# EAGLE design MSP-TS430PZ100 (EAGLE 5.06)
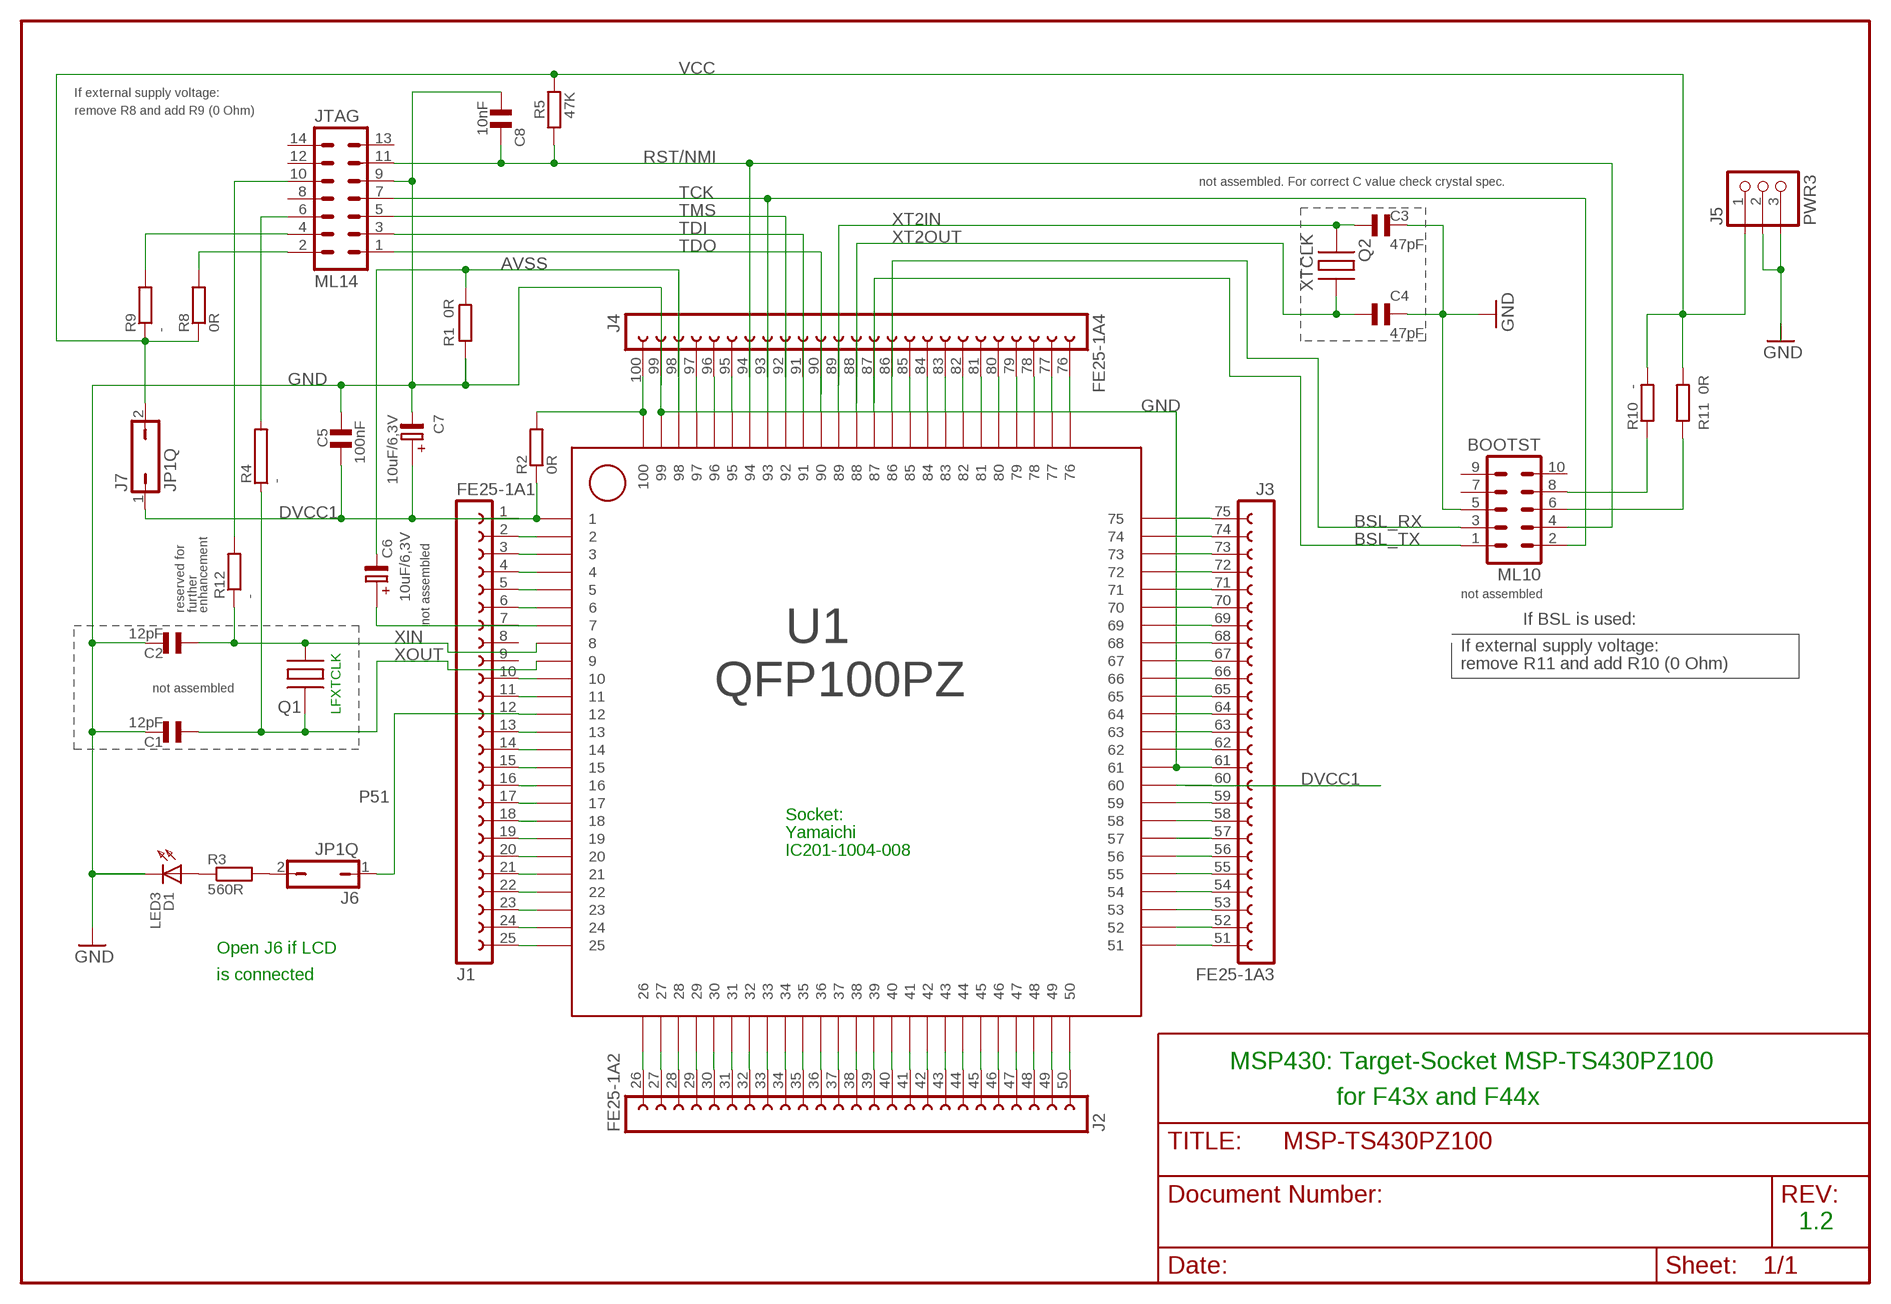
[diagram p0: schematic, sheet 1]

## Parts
BOOTST  ML10  [ML10]
C1  12pF  CSMD0805  [CSMD0805]
C2  12pF  CSMD0805  [CSMD0805]
C3  47pF  CSMD0805  [CSMD0805]
C4  47pF  CSMD0805  [CSMD0805]
C5  100nF  CSMD0805  [CSMD0805]
C6  10uF/6,3V  ELKO_1210  [1210ELKO]
C7  10uF/6,3V  ELKO_1210  [1210ELKO]
C8  10nF  CSMD0805  [CSMD0805]
D1  LED3  [LED3]
J1  FE25-1A1  [FE25-1A1]
J2  FE25-1A2  [FE25-1A2]
J3  FE25-1A3  [FE25-1A3]
J4  FE25-1A4  [FE25-1A4]
J5  PWR3  [PWR3]
J6  JP1Q  [JP1]
J7  JP1Q  [JP1]
JTAG  ML14  [ML14]
Q1  QUARZ3  [QUARZ3]
Q2  XTCLK  QUARZ2  [QUARZ2]
R1  0R  R_0805  [0805]
R2  0R  R_0805  [0805]
R3  560R  R_0805  [0805]
R4  -  SMD 0805 R  [SMD 0805]
R5  47K  R_0805  [0805]
R8  0R  R_0805  [0805]
R9  -  R_0805  [0805]
R10  -  R_0805  [0805]
R11  0R  R_0805  [0805]
R12  -  R_0805  [0805]
U1  QFP100PZ  [QFP100PZ]

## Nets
AVSS: C6.- J4.98 R1.2 U1.P98
BSL_RX: BOOTST.3 J4.86 U1.P86
BSL_TX: BOOTST.1 J4.87 U1.P87
DVCC1: C5.1 C7.+ J1.1 J3.60 J7.1 R2.1 U1.P1 U1.P60
GND: BOOTST.5 C1.2 C2.2 C3.2 C4.2 C5.2 C7.- C8.1 D1.K J3.61 J4.99 J5.2 J5.3 JTAG.9 R1.1 U1.P61 U1.P99
N$1: JTAG.6 R4.2
N$2: J4.96 U1.P96
N$3: JTAG.10 R12.2
N$4: J4.95 U1.P95
N$5: J4.83 U1.P83
N$6: J4.76 U1.P76
N$7: JTAG.2 R8.2
N$8: J4.85 U1.P85
N$9: J1.3 U1.P3
N$10: J4.84 U1.P84
N$11: J4.82 U1.P82
N$12: J1.4 U1.P4
N$13: J1.5 U1.P5
N$14: J4.81 U1.P81
N$15: J1.6 U1.P6
N$16: J2.46 U1.P46
N$17: J1.11 U1.P11
N$19: J1.13 U1.P13
N$20: J4.100 R2.2 U1.P100
N$21: J2.42 U1.P42
N$22: J1.14 U1.P14
N$23: JTAG.4 R9.2
N$24: J1.15 U1.P15
N$25: J1.16 U1.P16
N$26: J1.18 U1.P18
N$27: J1.19 U1.P19
N$28: J1.20 U1.P20
N$29: J1.17 U1.P17
N$30: J1.21 U1.P21
N$31: J1.22 U1.P22
N$32: J1.23 U1.P23
N$33: J6.2 R3.2
N$34: D1.A R3.1
N$36: J1.24 U1.P24
N$37: J1.25 U1.P25
N$38: J2.26 U1.P26
N$39: J2.27 U1.P27
N$40: J2.28 U1.P28
N$41: J2.29 U1.P29
N$42: BOOTST.8 R10.1
N$43: J2.30 U1.P30
N$44: J2.31 U1.P31
N$45: J2.32 U1.P32
N$46: J2.33 U1.P33
N$47: J2.34 U1.P34
N$48: J2.35 U1.P35
N$49: BOOTST.6 R11.1
N$50: J2.36 U1.P36
N$51: J2.37 U1.P37
N$52: J2.38 U1.P38
N$53: J1.2 U1.P2
N$54: J2.39 U1.P39
N$55: J2.40 U1.P40
N$56: J2.41 U1.P41
N$58: J2.43 U1.P43
N$59: J2.44 U1.P44
N$60: J2.45 U1.P45
N$62: J2.47 U1.P47
N$63: J2.48 U1.P48
N$64: J2.49 U1.P49
N$65: J2.50 U1.P50
N$66: J3.51 U1.P51
N$67: J3.52 U1.P52
N$68: J3.53 U1.P53
N$70: J3.54 U1.P54
N$71: J3.55 U1.P55
N$72: J3.56 U1.P56
N$73: J3.57 U1.P57
N$74: J3.58 U1.P58
N$75: J3.59 U1.P59
N$78: J3.62 U1.P62
N$79: J3.63 U1.P63
N$80: J4.80 U1.P80
N$81: J4.79 U1.P79
N$83: J3.64 U1.P64
N$84: J4.78 U1.P78
N$86: J4.77 U1.P77
N$87: J3.65 U1.P65
N$88: J3.66 U1.P66
N$89: J3.67 U1.P67
N$90: J3.68 U1.P68
N$91: J3.69 U1.P69
N$92: J3.70 U1.P70
N$93: J3.71 U1.P71
N$94: J3.72 U1.P72
N$95: J3.73 U1.P73
N$96: J3.74 U1.P74
N$97: J3.75 U1.P75
N$99: J1.10 U1.P10
N$100: J4.97 U1.P97
N$102: C6.+ J1.7 U1.P7
P51: J1.12 J6.1 U1.P12
RST/NMI: BOOTST.4 C8.2 J4.94 JTAG.11 R5.1 U1.P94
TCK: BOOTST.2 J4.93 JTAG.7 U1.P93
TDI: J4.91 JTAG.3 U1.P91
TDO: J4.90 JTAG.1 U1.P90
TMS: J4.92 JTAG.5 U1.P92
VCC: J5.1 J7.2 R5.2 R8.1 R9.1 R10.2 R11.2
XIN: C2.1 Q1.4 R12.1 U1.P8
XOUT: C1.1 Q1.3 R4.1 U1.P9
XT2IN: C3.1 J4.89 Q2.P$1 U1.P89
XT2OUT: C4.1 J4.88 Q2.P$4 U1.P88
Unconnected: BOOTST.7 BOOTST.9 BOOTST.10 J1.8 J1.9 JTAG.8 JTAG.12 JTAG.13 JTAG.14

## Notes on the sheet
- If external supply voltage:
- remove R8 and add R9 (0 Ohm)
- not assembled. For correct C value check crystal spec.
- not assembled
- reserved for | further | enhancement
- not assembled | If BSL is used:
- If external supply voltage:
- remove R11 and add R10 (0 Ohm)
- not assembled
- LFXTCLK
- Socket:
- Yamaichi
- IC201-1004-008
- Open J6 if LCD
- is connected
- MSP430: Target-Socket MSP-TS430PZ100
- for F43x and F44x
- 1.2

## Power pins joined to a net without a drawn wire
GND: Q1.GND@1(GND) Q1.GND@2(GND) Q1.GND@3(GND) Q2.GND Q2.GND2(GND)

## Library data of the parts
BOOTST = con-ml:ML10
C1-C5 C8 = cap:CSMD0805
C6 C7 = smd:ELKO_1210
D1 = led:LED3
J1 = CON-LSTA:FE25-1A1
J2 = CON-LSTA:FE25-1A2
J3 = CON-LSTA:FE25-1A3
J4 = CON-LSTA:FE25-1A4
J5 = MSP430:PWR3
J6 J7 = jumps:JP1Q
JTAG = con-ml:ML14
Q1 = MSP430:QUARZ3
Q2 = MSP430:QUARZ2
R1-R3 R5 R8-R12 = smd:R_0805
R4 = flash-evk:SMD 0805 R
U1 = MSP430:QFP100PZ

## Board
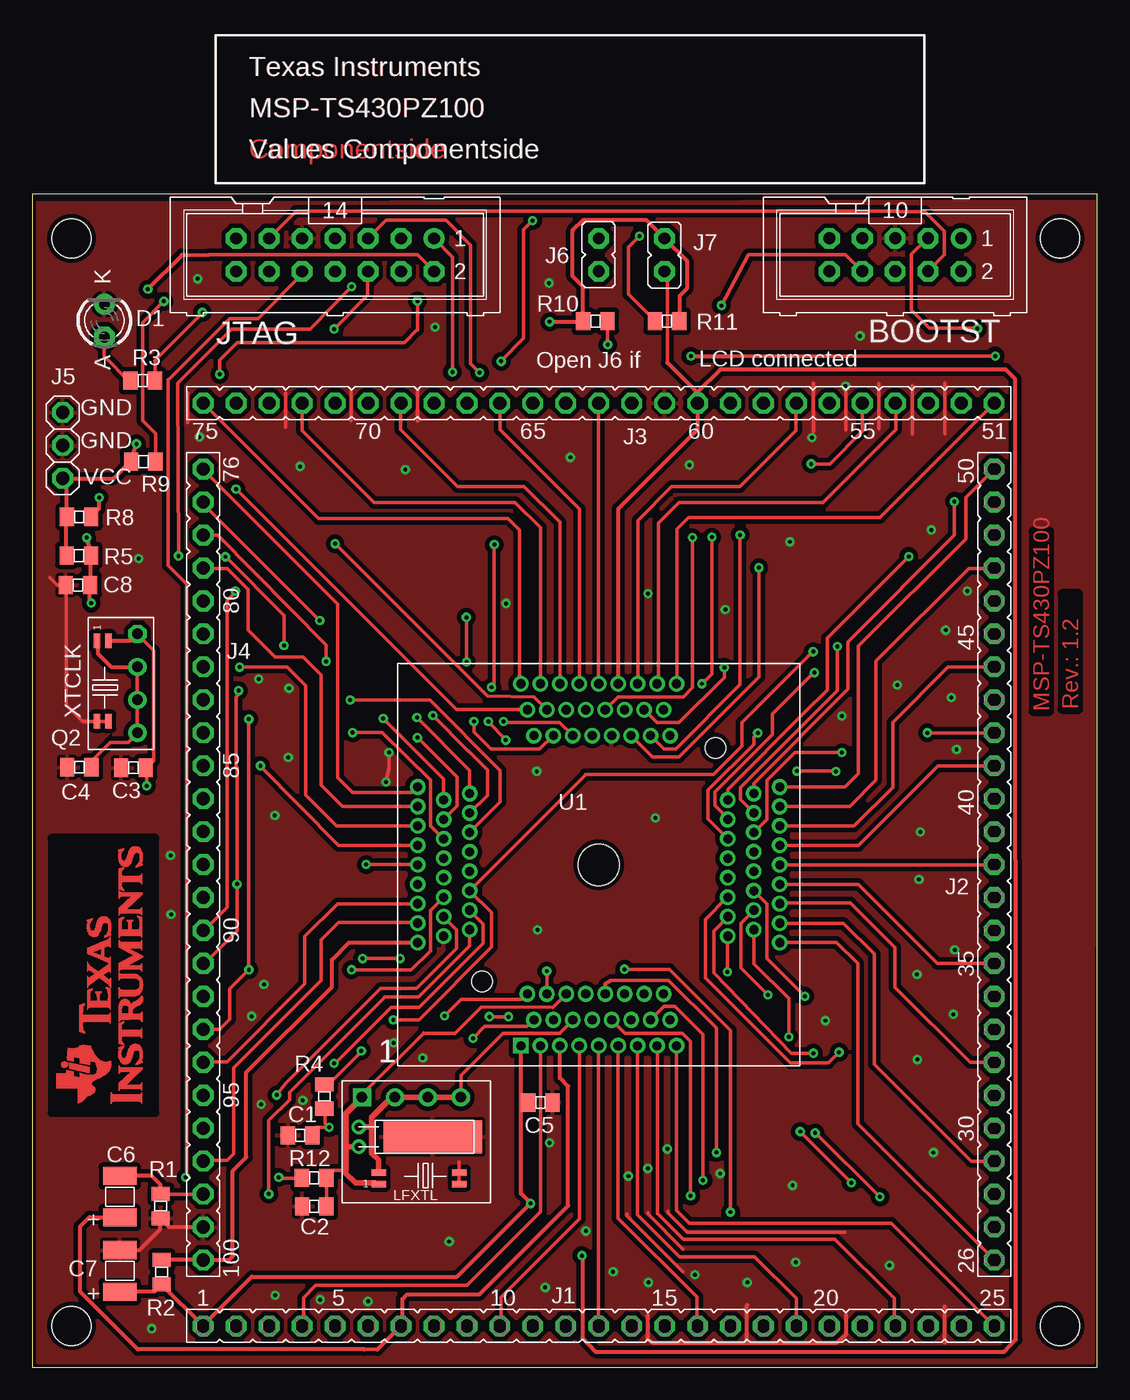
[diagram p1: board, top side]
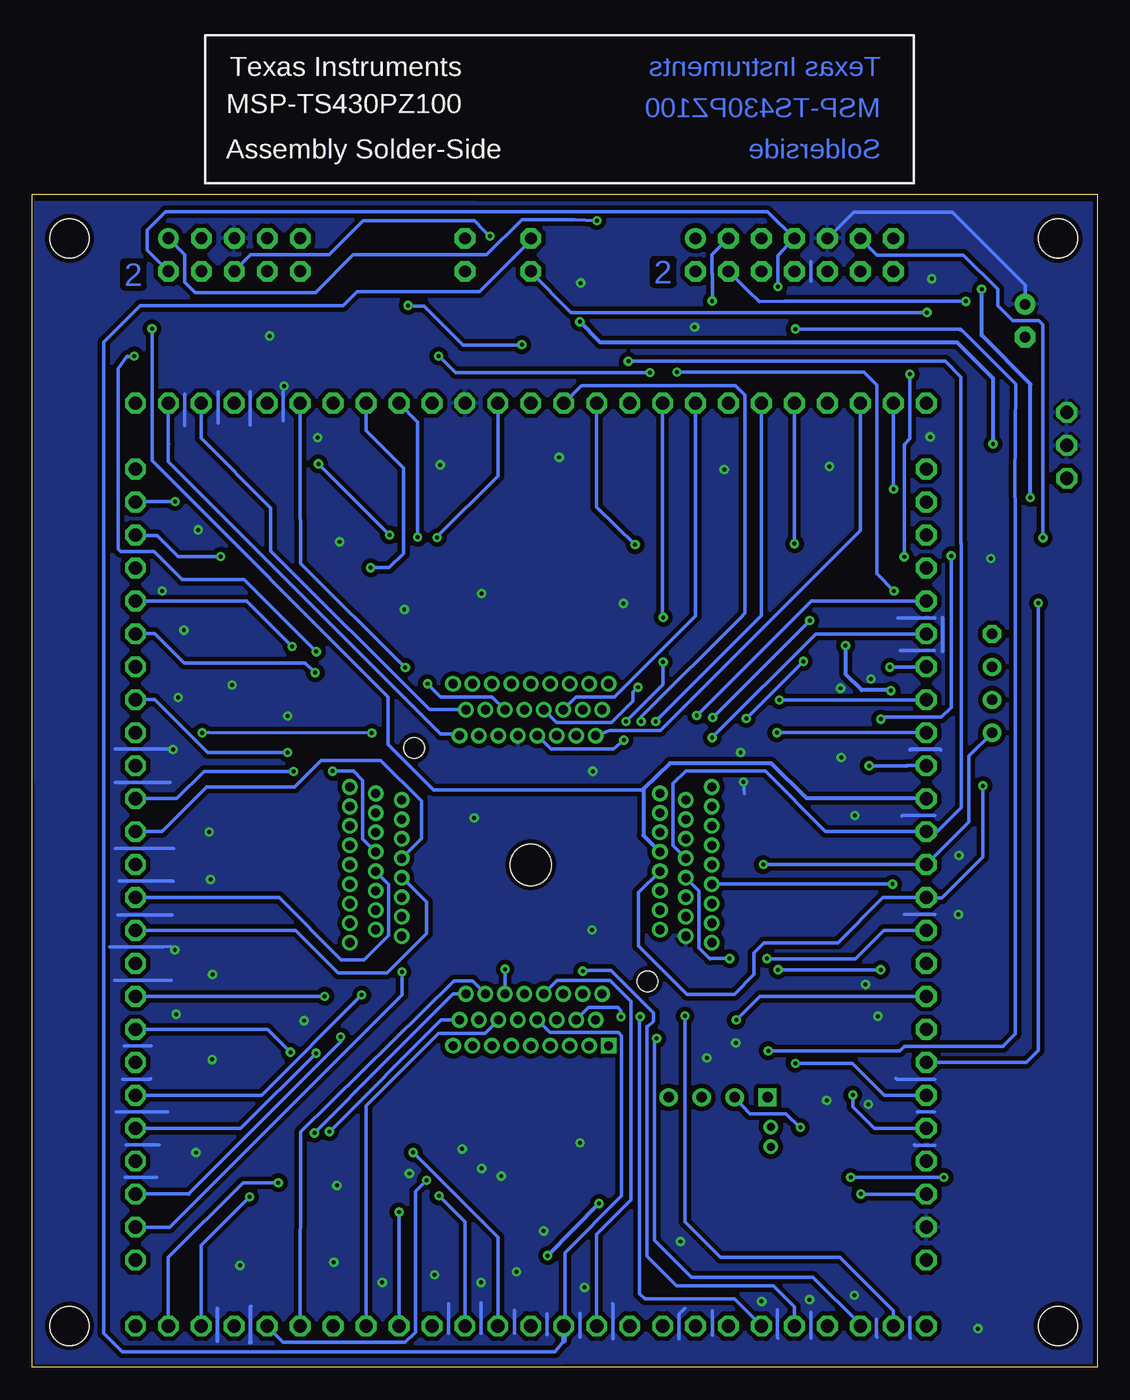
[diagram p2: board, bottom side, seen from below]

Size 82.07 x 90.41 mm. Coordinates in mm from the lower left corner, seen from the top.
Outline: 0,0 82.06,0 82.06,90.41 0,90.41 0,0
Copper layers (1*16): Top 0.035mm / dielectric 1.5mm / Bottom 0.035mm
Design rules "default": minimum track width 8mil, minimum drill 12mil, track to track 8mil, track to pad 8mil, pad to pad 8mil, via to via 8mil, smd to smd 8mil, copper to edge 0mil, drill to drill 8mil, minimum pad ring 10mil, minimum via ring 8mil, stop-mask expansion 0mil, vias tented up to drill 0mil, thermal gap 10mil
Holes 3 mm at 3.01,3.17 3.01,86.99 79.21,3.17 79.21,86.99
tRestrict: area 1.5,19.6 to 9.4,40.8; area 44.1,49.3 to 45.7,49.9
bRestrict: area 44.1,49.3 to 45.8,49.9

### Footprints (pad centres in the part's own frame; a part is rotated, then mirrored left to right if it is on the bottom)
ML10 = drill 0.914 pad 1.6 round: 1 -5.08,-1.27 | drill 0.914 pad 1.6 octagon: 2 -5.08,1.27; 3 -2.54,-1.27; 4 -2.54,1.27; 5 0,-1.27; 6 0,1.27; 7 2.54,-1.27; 8 2.54,1.27; 9 5.08,-1.27; 10 5.08,1.27
CSMD0805 = smd 1.092 x 1.397: 1 -0.94,0; 2 0.94,0
1210ELKO = smd 1.397 x 2.591: + 1.6,0; - -1.6,0
LED3 = drill 0.813 pad 1.6 octagon: A -1.27,0 | drill 0.813 pad 1.6 round: K 1.27,0
FE25-1A1 = drill 1.016 pad 1.6 octagon: 1 -30.48,0; 2 -27.94,0; 3 -25.4,0; 4 -22.86,0; 5 -20.32,0; 6 -17.78,0; 7 -15.24,0; 8 -12.7,0; 9 -10.16,0; 10 -7.62,0; 11 -5.08,0; 12 -2.54,0; 13 0,0; 14 2.54,0; 15 5.08,0; 16 7.62,0; 17 10.16,0; 18 12.7,0; 19 15.24,0; 20 17.78,0; 21 20.32,0; 22 22.86,0; 23 25.4,0; 24 27.94,0; 25 30.48,0
FE25-1A2 = drill 1.016 pad 1.6 octagon: 26 -30.48,0; 27 -27.94,0; 28 -25.4,0; 29 -22.86,0; 30 -20.32,0; 31 -17.78,0; 32 -15.24,0; 33 -12.7,0; 34 -10.16,0; 35 -7.62,0; 36 -5.08,0; 37 -2.54,0; 38 0,0; 39 2.54,0; 40 5.08,0; 41 7.62,0; 42 10.16,0; 43 12.7,0; 44 15.24,0; 45 17.78,0; 46 20.32,0; 47 22.86,0; 48 25.4,0; 49 27.94,0; 50 30.48,0
FE25-1A3 = drill 1.016 pad 1.6 octagon: 51 -30.48,0; 52 -27.94,0; 53 -25.4,0; 54 -22.86,0; 55 -20.32,0; 56 -17.78,0; 57 -15.24,0; 58 -12.7,0; 59 -10.16,0; 60 -7.62,0; 61 -5.08,0; 62 -2.54,0; 63 0,0; 64 2.54,0; 65 5.08,0; 66 7.62,0; 67 10.16,0; 68 12.7,0; 69 15.24,0; 70 17.78,0; 71 20.32,0; 72 22.86,0; 73 25.4,0; 74 27.94,0; 75 30.48,0
FE25-1A4 = drill 1.016 pad 1.6 octagon: 76 -30.48,0; 77 -27.94,0; 78 -25.4,0; 79 -22.86,0; 80 -20.32,0; 81 -17.78,0; 82 -15.24,0; 83 -12.7,0; 84 -10.16,0; 85 -7.62,0; 86 -5.08,0; 87 -2.54,0; 88 0,0; 89 2.54,0; 90 5.08,0; 91 7.62,0; 92 10.16,0; 93 12.7,0; 94 15.24,0; 95 17.78,0; 96 20.32,0; 97 22.86,0; 98 25.4,0; 99 27.94,0; 100 30.48,0
PWR3 = drill 1.016 pad 1.6 octagon: 1 -2.54,0; 2 0,0; 3 2.54,0
JP1 = drill 0.914 pad 1.6 octagon: 1 0,-1.27; 2 0,1.27
ML14 = drill 0.914 pad 1.6 round: 1 -7.62,-1.27 | drill 0.914 pad 1.6 octagon: 2 -7.62,1.27; 3 -5.08,-1.27; 4 -5.08,1.27; 5 -2.54,-1.27; 6 -2.54,1.27; 7 0,-1.27; 8 0,1.27; 9 2.54,-1.27; 10 2.54,1.27; 11 5.08,-1.27; 12 5.08,1.27; 13 7.62,-1.27; 14 7.62,1.27
QUARZ3 = drill 0.813 pad 1.397 round: 1 -3.81,-1.27; 2 -1.27,-1.27; 3 1.27,-1.27 | drill 0.813 pad 1.397 square: 4 3.81,-1.27 | drill 0.61 pad 1.016 round: 5 4.064,1.016; 6 4.064,2.54 | smd 1.1 x 0.5: 7 2.517,4.513; 8 2.513,5.409; GND@1 -3.687,5.409; GND@2 -3.687,4.51 | smd 7.62 x 2.54: GND@3 -1.651,1.778
QUARZ2 = smd 1.1 x 0.5: GND -2.925,1.853; GND2 -2.925,0.954; P$7 3.275,1.853; P$8 3.279,0.958 | drill 0.813 pad 1.397 octagon: P$1 3.81,-1.27 | drill 0.813 pad 1.397 round: P$2 1.27,-1.27; P$3 -1.27,-1.27; P$4 -3.81,-1.27
0805 = smd 1.092 x 1.397: 1 -0.94,0; 2 0.94,0
SMD 0805 = smd 1.092 x 1.397: 1 -0.94,0; 2 0.94,0
QFP100PZ = drill 0.7 pad 1 square: P1 -6,-13.95 | drill 0.7 pad 1 round: P2 -5.5,-9.95; P3 -5,-11.95; P4 -4.5,-13.95; P5 -4,-9.95; P6 -3.5,-11.95; P7 -3,-13.95; P8 -2.5,-9.95; P9 -2,-11.95; P10 -1.5,-13.95; P11 -1,-9.95; P12 -0.5,-11.95; P13 0,-13.95; P14 0.5,-9.95; P15 1,-11.95; P16 1.5,-13.95; P17 2,-9.95; P18 2.5,-11.95; P19 3,-13.95; P20 3.5,-9.95; P21 4,-11.95; P22 4.5,-13.95; P23 5,-9.95; P24 5.5,-11.95; P25 6,-13.95; P26 13.95,-6; P27 9.95,-5.5; P28 11.95,-5; P29 13.95,-4.5; P30 9.95,-4; P31 11.95,-3.5; P32 13.95,-3; P33 9.95,-2.5; P34 11.95,-2; P35 13.95,-1.5; P36 9.95,-1; P37 11.95,-0.5; P38 13.95,0; P39 9.95,0.5; P40 11.95,1; P41 13.95,1.5; P42 9.95,2; P43 11.95,2.5; P44 13.95,3; P45 9.95,3.5; P46 11.95,4; P47 13.95,4.5; P48 9.95,5; P49 11.95,5.5; P50 13.95,6; P51 6,13.95; P52 5.5,9.95; P53 5,11.95; P54 4.5,13.95; P55 4,9.95; P56 3.5,11.95; P57 3,13.95; P58 2.5,9.95; P59 2,11.95; P60 1.5,13.95; P61 1,9.95; P62 0.5,11.95; P63 0,13.95; P64 -0.5,9.95; P65 -1,11.95; P66 -1.5,13.95; P67 -2,9.95; P68 -2.5,11.95; P69 -3,13.95; P70 -3.5,9.95; P71 -4,11.95; P72 -4.5,13.95; P73 -5,9.95; P74 -5.5,11.95; P75 -6,13.95; P76 -13.95,6; P77 -9.95,5.5; P78 -11.95,5; P79 -13.95,4.5; P80 -9.95,4; P81 -11.95,3.5; P82 -13.95,3; P83 -9.95,2.5; P84 -11.95,2; P85 -13.95,1.5; P86 -9.95,1; P87 -11.95,0.5; P88 -13.95,0; P89 -9.95,-0.5; P90 -11.95,-1; P91 -13.95,-1.5; P92 -9.95,-2; P93 -11.95,-2.5; P94 -13.95,-3; P95 -9.95,-3.5; P96 -11.95,-4; P97 -13.95,-4.5; P98 -9.95,-5; P99 -11.95,-5.5; P100 -13.95,-6 | hole 3.2: 0,0 | hole 1.6: -9,-9; 9,9

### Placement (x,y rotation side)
BOOTST  66.5,85.72 180 top
C1  20.63,17.87 180 top
C2  21.72,12.39 180 top
C3  7.79,46.19 180 top
C4  3.62,46.23 180 top
C5  39.15,20.39 0 top
C6  6.74,13.13 270 top
C7  6.74,7.42 270 top
C8  3.51,60.27 0 top
D1  5.55,80.65 90 top
J1  43.65,3.17 0 top
J2  74.13,38.73 90 top
J3  43.65,74.29 180 top
J4  13.17,38.73 270 top
J5  2.33,71.04 90 top
J6  43.65,85.72 180 top
J7  48.73,85.71 0 top
JTAG  23.33,85.72 180 top
Q1  29.21,19.52 180 top
Q2  6.82,52.69 90 top
R1  9.89,12.4 90 top
R2  9.98,7.32 90 top
R3  8.5,76.03 0 top
R4  22.5,20.86 90 top
R5  3.58,62.55 180 top
R8  3.6,65.53 0 top
R9  8.55,69.78 0 top
R10  43.4,80.61 180 top
R11  48.92,80.61 0 top
R12  21.71,14.57 180 top
U1  43.65,38.71 0 top
U$1  [ORI2_2CM]  8.5,20.32 90 top
U$2  [2LAGEN]  14.14,91.23 0 top

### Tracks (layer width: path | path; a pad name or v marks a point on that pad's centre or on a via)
AVSS  (via drill 0.3)
  Top 0.254: U1.P98 33.7,32.45 29.77,28.52 27.17,28.52 | v18.22,13.34 18.22,19.01 19.82,20.61 19.82,21.18 27.17,28.52 | 27.17,28.52 27.16,28.52 | J4.98 13.18,13.32 13.17,13.31 9.89,13.31
  Top 0.305: C6.- 9.18,14.73 9.87,14.04 9.87,13.33 9.89,13.31 | 9.89,13.31 9.92,13.28 | R1.2 9.89,13.31
  Bottom 0.254: v18.22,13.34 v18.21,13.34 18.21,13.34 18.2,13.33 | 18.2,13.33 18.2,13.34 | 18.2,13.33 18.19,13.33 18.18,13.32 18.16,13.33 J4.98
BSL_RX  (via drill 0.3)
  Top 0.254: v72.85,80.03 72.8,80.08 69.14,80.08 67.77,81.45 67.77,85.77 68.93,86.94 69.04,86.94 BOOTST.3
  Bottom 0.254: 34.98,44.55 35.03,44.49 51.14,44.49 54.65,48 54.65,51.66 72.85,69.86 v72.85,80.03
  Bottom 0.305: J4.86 13.19,43.83 22.37,43.83 25.12,46.53 32.94,46.53 34.98,44.55 34.98,40.99 U1.P86 | U1.P86 | U1.P86
BSL_TX  (via drill 0.3)
  Top 0.254: v38.55,88.36 37.87,87.66 37.87,79.3 v36.14,77.52
  Bottom 0.254: U1.P87 32.69,40.21 32.69,44.97 31.71,45.96 25.58,45.96 20.94,41.27 13.16,41.27 | BOOTST.1 70.32,85.74 70.32,83.61 69.54,82.82 60.23,82.82 57.33,85.72 47.05,85.72 44.33,88.44 40.29,88.44 v38.55,88.36 | v36.14,77.52 12.11,77.52 11.69,77.52 10.49,76.31 10.49,63.9 10.5,63.88 10.5,63.48 10.48,63.45 10.48,43.12 12.31,41.29 13.14,41.29 13.16,41.27 | 13.16,41.27 13.15,41.27 | 13.16,41.27 J4.87 | 13.16,41.27
DVCC1  (via drill 0.3)
  Top 0.254: 37.7,24.84 37.65,24.79 U1.P1 37.65,24.73 37.64,24.72 37.66,24.69 37.66,20.42 37.7,20.39 C5.1 | 38.39,12.63 38.38,12.63 v38.38,12.6 | v38.38,12.6 | 38.39,12.63 | 38.39,12.63 v38.39,12.61 v38.38,12.61 v38.39,12.62 38.39,12.64 | v38.38,12.6 38.38,12.62 38.39,12.63 | 16.91,6.96 16.91,6.97 | J1.1 13.17,3.23 13.11,3.23 | 9.97,6.36 R2.1 9.42,5.82 | 51.34,75.05 51.27,75.12 51.29,75.11 51.27,75.09 J3.60 | J7.1 48.73,84.42 48.7,84.4 48.93,84.07 48.93,77.41
  Top 0.305: U1.P60 45.15,66.14 51.27,72.26 51.27,75.12 | 51.27,75.12 51.27,75.15 53.02,76.9 75.01,76.9 75.76,76.15 75.81,2.14 74.9,1.19 43.41,1.19 42.39,2.26 42.39,8.6 v42.36,8.59 | U1.P1 37.65,13.38 38.39,12.64 | 16.91,6.97 32.73,6.97 38.38,12.63 | 16.91,6.96 13.17,3.23 | 13.11,3.23 9.97,6.36 | 9.42,5.82 C7.+ | 51.27,75.12 48.93,77.41
  Bottom 0.254: v38.39,12.61 v38.38,12.61
  Bottom 0.305: v38.39,12.61 v42.36,8.59
GND  (via drill 0.3)
  Top 0.254: J4.99 13.15,10.79 13.05,10.89 | Q2.GND Q2.GND2 | Q2.GND 4.96,49.79 | Q2.GND 3.86,49.77 2.59,51.04 2.59,60.25 C8.1 1.9,60.27 1.34,60.83 | v27.48,47.37 27.48,46.19 v27.26,45.1 | 19.53,72.44 19.53,75.06 | 24.57,72.95 24.57,75.19 | 11.96,72.78 11.96,75.06 | 29.69,72.91 29.69,75.23 | 60.19,72.11 60.19,75.84 | 62.72,72.2 62.72,75.65 | 65.24,72.35 65.24,75.79 | 67.81,71.91 67.81,75.65 | 70.34,71.96 70.34,75.84 | 45.83,11.81 45.83,11.66 50.15,7.35 | 48.98,12 48.98,11.91 50.49,10.4 62.62,10.4 | 47.43,11.91 47.43,11.81 50.15,9.09 | 9.87,11.45 9.88,11.46 R1.1 9.89,11.42 9.82,11.35 | 8.25,9.02 C7.- | Q1.GND@1 Q1.GND@2 32.88,15.02 32.88,15.82 | D1.K
  Top 0.305: J4.99 10.53,10.79 9.87,11.45 | 8.25,9.02 9.82,10.59 9.82,11.35 | 47.44,3.96 47.44,2.15 47.77,1.88 55.08,1.88 | 55.08,1.88 62.01,1.88 62.73,2.53 62.73,4.01 | 55.08,1.88 55.08,4.77 | 70.32,1.88 70.32,4.67
  Bottom 0.254: D1.K 5.55,83.41 11.17,89.03 18.75,89.03 JTAG.9 | J4.99 | v27.26,45.1 27.2,44.21 | 29.67,2.45 29.67,4.34 | 39.86,2.3 39.86,4.14 | 42.38,2.49 42.38,4.09 | 44.91,2.59 44.91,4.39 | 47.48,2.59 47.48,4.97 | 50,2.59 50,4.87 | 72.47,14.62 74.9,14.62 | 72.28,17.14 74.85,17.14 | 72.91,24.76 75,24.76 | 75.09,22.19 73,22.19 72.96,22.24 | 12.49,22.19 15.45,22.19 15.5,22.24 | 12.54,19.67 13.85,19.67 | 12.49,17.1 14.04,17.1 14.09,17.14 | 14.87,34.9 12.49,34.9 | 12.49,42.52 15.01,42.52 15.06,42.47 | 12.54,55.22 15.16,55.22 | 15.35,57.75 12.49,57.75 | 71.16,47.62 75.67,47.62 | 71.45,45.05 75.67,45.05 | 71.16,39.96 75.67,39.96 | 75.38,37.48 71.26,37.48 71.21,37.43 | 71.31,34.86 75.48,34.86 | 76.11,32.39 71.99,32.39 71.4,32.44 | 71.36,29.81 75.72,29.81 | 71.64,19.67 75.62,19.67 | 37.31,2.2 37.31,4.84 37.36,4.89 | 32.23,2.2 32.23,4.08 31.77,4.54 | 22.06,83.69 22.06,85.21 | 62.73,72.96 62.73,75.2 | 65.27,72.61 65.27,75.2 | 67.76,72.76 67.76,75.2 | 70.35,72.56 70.35,75 | 14.44,3.84 14.44,2.28 14.39,2.23 | 17.01,3.69 17.01,2.33 16.96,2.28 | 22.07,2.23 22.07,4.23 | 24.65,4.42 24.65,2.28 24.6,2.23
  Bottom 0.305: 12.05,47.59 14.41,47.59 | 11.9,55.16 11.9,57.76 | 65.29,1.88 65.24,1.92 65.24,4.67 | 67.8,2 67.8,4.52
  other vias: 58.6,13.99 68.21,23.7 58.83,8.07 66.07,7.83 51.07,7.1 55.1,6.52 44.76,7.35 47.48,6.52 39.52,6.13 45.93,14.72 47.43,15.3 48.94,16.81 39.86,17.29 53.01,14.91 17.63,20.25 20.64,69.42 28.74,69.17 17.85,29.49 16.91,27.04 38.94,33.69 48.01,42.32 41.46,70.12 50.63,69.53 36.51,58.86 53.4,58.38 61.12,26.7 39.81,83.55 31.03,80.16 12.73,83.88 70.39,56.8 18.68,42.51 10.68,34.89 19.72,46.98 17.44,53.03 19.77,52.32 70.98,27.2 68.19,30.27 71.08,32.15 68.34,37.59 68.44,41.24 71.23,47.59 70.83,51.61 66.66,52.57 38.87,45.92 69.46,16.53 60.08,71.64 63.79,79.47 62.67,75.61 58.39,63.61 8.19,62.31 12.87,71.69 32.12,9.67 20.84,20.55 69.28,64.52 72.06,59.81 30.09,23.83 27.85,25 10.64,39.43 9.18,2.96 18.71,5.54 22.16,5.2 25.86,5.05 47.44,59.61 62.39,50.18 42.65,10.49
  pour Top (isolate 0.356): 0.41,0.38 81.76,0.38 81.8,64.38 81.8,89.82 0.41,89.72
  pour Bottom (isolate 0.356): 0.47,0.38 81.74,0.3 81.79,89.8 13.8,89.72 0.47,89.72
N$1  (via drill 0.3)
  Top 0.254: v23.26,80.01 v23.25,80.01 25.85,82.62 25.85,84.44 25.86,84.45 JTAG.6 | v25.35,24.38 25.4,24.38 22.89,21.87 22.52,21.87 22.52,21.82 R4.2
  Bottom 0.254: v23.26,80.01 10.53,80.01 10.53,79.93 10.44,79.93 6.28,75.77 6.33,68.04 6.31,65.98 6.31,58.15 6.3,58.14 6.31,58.14 6.31,25.68 7.22,24.77 7.22,24.72 7.35,24.72 14.87,24.72 15.21,24.38 v25.35,24.38
N$2  (via drill 0.3)
  Top 0.254: U1.P96 32.71,33.7 32.71,32.27 29.63,29.19 26.84,29.19 26.83,29.2 19.54,21.92 v18.83,20.96
  Bottom 0.254: v18.83,20.96 18.81,20.95 18.81,20.04 17.18,18.41 J4.96
N$3  (via drill 0.3)
  Top 0.254: JTAG.10 20.84,84.44 20.84,84.27 17.38,80.82 15.19,80.82 10.49,76.11 10.48,76.11 10.48,61.78 11.9,60.35 11.9,14.76 v11.81,14.62 | 20.79,14.55 | 20.79,14.55 R12.2 | v18.99,14.62 19.02,14.55 20.79,14.55
  Bottom 0.254: v18.99,14.62 v11.81,14.62 11.87,14.52
N$4  (via drill 0.3)
  Top 0.254: U1.P95 34.74,34.17 34.74,32.65 29.79,27.7 27.65,27.7 27.63,27.73 23.31,23.41 v23.26,23.41
  Bottom 0.254: J4.95 16.39,20.95 18.85,23.41 v23.26,23.41
N$5  (via drill 0.3)
  Top 0.254: v24.5,51.42 30.65,51.42 36.05,45.98 36.05,43.56 U1.P83
  Bottom 0.254: J4.83 24.49,51.43 v24.5,51.42
N$6
  Top 0.254: 13.11,69.21 12.99,69.34 | 13.11,69.21 J4.76 | 13.11,69.21 23.53,58.8 23.53,45.42 24.24,44.71 24.25,44.71 24.69,44.27 29.26,44.27 U1.P76
N$7  (via drill 0.3)
  Top 0.254: JTAG.2 | JTAG.2 | JTAG.2 29.67,85.72 13.58,85.72 11.54,85.72 11.49,85.72 11.49,85.67 | R8.2 5.14,66.15
  Top 0.305: 5.14,66.15 v5.14,67.01 | v8.9,83.08 11.49,85.67
  Bottom 0.305: v5.14,67.01 5.14,75.76 8.9,79.52 v8.9,83.08
N$8  (via drill 0.3)
  Top 0.254: U1.P85 23.6,40.21 v17.57,46.34
  Bottom 0.254: v17.57,46.34 14.66,46.34 14.65,46.35 J4.85
N$9  (via drill 0.3)
  Top 0.254: U1.P3 38.13,26.24 34.87,26.24 v33.95,25.33
  Bottom 0.254: v33.95,25.33 34.1,25.23 34.1,9.77 31.26,6.93 21.9,6.93 18.23,3.25 18.25,3.23 J1.3
N$10  (via drill 0.3)
  Top 0.254: v24.68,48.89 26.97,48.91 30.68,45.23 30.69,41.71 U1.P84
  Bottom 0.254: J4.84 v24.68,48.89
N$11  (via drill 0.3)
  Top 0.254: U1.P82 23.44,41.72 21.07,44.08 21.07,52.52 19.65,53.94 v15.96,53.94
  Bottom 0.254: J4.82 13.14,53.96 | J4.82 | v15.96,53.94 15.94,53.96 J4.82
N$12
  Top 0.254: J1.4 20.9,3.3 20.9,5.35 21.83,6.28 33.48,6.28 39.15,11.95 39.14,11.95 39.14,11.96 39.15,11.97 39.16,24.31 U1.P4 | J1.4
N$13  (via drill 0.3)
  Top 0.254: U1.P5 39.65,28.74 39.64,28.73 v39.64,30.51
  Bottom 0.254: J1.5 23.33,4.64 24.96,6.27 32.43,6.27 34.71,8.55 34.71,26.24 34.61,26.24 34.21,26.65 34.21,27.31 37.46,30.56 39.59,30.56 v39.64,30.51
N$14  (via drill 0.3)
  Top 0.254: v29.67,48.51 32.71,45.47 32.71,43.23 U1.P81 | U1.P81 | U1.P81
  Bottom 0.254: J4.81 21.67,56.51 v29.67,48.51
N$15  (via drill 0.3)
  Top 0.254: v35.22,27 v36.7,27
  Bottom 0.254: U1.P6 39.19,27.72 36.95,27.72 36.7,27.46 v36.7,27 | v35.22,27 35.27,26.8 35.27,5.66 34.87,5.25 27.96,5.25 25.92,3.22 25.87,3.22 J1.6
N$16  (via drill 0.3)
  Top 0.254: U1.P46 54.58,43.73 54.58,44.69 59.55,49.64 62.05,52.13 v62.05,55.53 v62.04,55.54
  Bottom 0.254: v62.04,55.54 65.54,59.04 74.09,59.04 74.09,59.03 74.1,59.04 J2.46 | J2.46 | J2.46
N$17
  Bottom 0.254: 38.57,3.1 J1.11 38.57,10.24 35.93,12.88 35.93,28.17 37.56,29.8 41.63,29.8 42.66,28.76 | 42.66,28.76 42.69,28.73 | 42.66,28.76 U1.P11
N$19
  Top 0.254: 43.72,24.76 43.72,24.77 | 43.72,24.76 U1.P13 | J1.13 43.65,24.69 43.72,24.76
N$20
  Top 0.254: U1.P100 | J4.100 | 23.09,31.4 23.08,31.39 | 15.44,8.54 15.44,8.55 | R2.2 10.01,8.26 10.02,8.25
  Top 0.305: U1.P100 24.41,32.71 23.08,31.39 | 23.09,31.4 23.09,29.3 16.49,22.7 16.49,16.17 15.44,15.12 15.44,8.55 | J4.100 15.15,8.25 15.44,8.54 | J4.100 10.02,8.25
N$21  (via drill 0.3)
  Top 0.254: U1.P42 52.09,42.23 52.09,44.46 55.6,47.98 55.6,48.56 v55.91,48.87 | J2.42 74.12,48.89 74.11,48.88 v68.98,48.88
  Bottom 0.254: v55.91,48.87 68.46,48.89 v68.98,48.88
N$22  (via drill 0.3)
  Top 0.254: v52.72,16.53 52.72,26.13 49.03,29.82 44.59,29.82 44.15,29.53 44.15,28.8 44.14,28.79 44.15,28.78 U1.P14
  Bottom 0.254: J1.14 46.19,10 v52.72,16.53
N$23  (via drill 0.3)
  Top 0.254: R9.2 9.49,71.95 8.49,72.95 8.49,80.5 v10.13,82.14
  Bottom 0.254: v10.13,82.14 24.08,82.14 26.04,82.11 26.92,82.96 JTAG.4 | JTAG.4 | JTAG.4
N$24  (via drill 0.3)
  Top 0.254: U1.P15 45.69,25.72 50.11,25.72 50.72,25.12 50.72,23 50.73,22.99 v50.73,13.19
  Bottom 0.254: J1.15 48.73,11.19 v50.73,13.19
N$25
  Top 0.254: J1.16 51.22,3.12 51.22,5.4 45.15,11.47 45.15,24.71 45.1,24.76 | 45.1,24.76 45.09,24.77 | 45.1,24.76 U1.P16
N$26
  Bottom 0.254: J1.18 56.35,20.13 50.75,25.73 47.19,25.73 U1.P18 | U1.P18 | U1.P18
N$27
  Top 0.254: J1.19 58.83,3.24 58.88,3.3 58.88,5.29 55.66,8.51 49.87,8.51 46.65,11.73 46.65,24.75 46.66,24.76 | 46.66,24.76 46.67,24.77 | 46.66,24.76 U1.P19
N$28
  Bottom 0.254: U1.P20 48.15,29.76 49.56,29.76 61.38,18.14 J1.20
N$29  (via drill 0.3)
  Top 0.254: v53.82,11.96 v53.81,11.95 53.81,25.95 49.1,30.66 v45.64,30.66
  Bottom 0.254: J1.17 v53.81,11.95 | 45.65,28.67 45.69,28.63 | 45.65,28.67 U1.P17 | v45.64,30.66 45.64,28.68 45.65,28.67
N$30  (via drill 0.3)
  Top 0.254: U1.P21 48.67,27.79 49.53,27.79 51.7,25.62 51.7,22.63 51.69,22.62 v51.69,14.4
  Bottom 0.254: v51.69,14.4 52.55,13.54 52.55,2.67 53.34,1.9 62.74,1.9 63.99,3.16 J1.21
N$31
  Top 0.254: J1.22 66.51,3.22 66.43,3.3 66.43,5.29 61.87,9.85 50.16,9.85 48.17,11.84 48.17,11.82 48.18,11.82 48.18,24.77 48.17,24.76 U1.P22
N$32  (via drill 0.3)
  Top 0.254: v60.33,18.04 65.31,13.11 v65.33,13.11
  Bottom 0.254: U1.P23 49.66,28.76 54.82,23.61 v60.33,18.04 | J1.23 69.05,9.39 v65.33,13.11 | J1.23
N$33  (via drill 0.3)
  Top 0.254: v13.11,81.28 9.44,77.59 9.46,77.57 9.46,76.06 R3.2
  Bottom 0.254: 43.7,84.45 43.73,84.48 | 43.7,84.45 J6.2 | v13.11,81.28 40.56,81.28 43.7,84.45
N$34
  Top 0.254: D1.A 5.53,79.4 5.53,77.9 7.47,75.96 7.58,75.96 7.58,76.01 R3.1
N$36  (via drill 0.3)
  Top 0.254: v59.18,18.15 v63.12,14.21
  Bottom 0.254: U1.P24 50.56,26.76 v59.18,18.15 | v63.12,14.21 65.84,14.21 71.59,8.46 J1.24
N$37
  Top 0.254: J1.25 74.11,3.17 66.2,11.08 50.63,11.08 49.65,12.06 49.65,24.73 49.68,24.76 | 49.68,24.76 49.75,24.84 | 49.68,24.76 U1.P25
N$38
  Top 0.254: J2.26 63.62,18.76 63.62,31.11 61.95,32.73 57.83,32.73 57.76,32.8 57.68,32.71 U1.P26
N$39  (via drill 0.3)
  Top 0.254: U1.P27 53.53,33.21 53.52,33.21 53.58,33.16 v53.58,30.46
  Bottom 0.254: J2.27 71.47,10.79 53.58,28.68 v53.58,30.46
N$40  (via drill 0.3)
  Top 0.254: U1.P28 55.62,33.69 55.62,31.09 58.3,28.41 v58.3,25.45
  Bottom 0.254: J2.28 | J2.28 | 70.02,13.34 J2.28 | 70.02,13.34 70.04,13.31 | 70.02,13.34 69.98,13.34 | v58.3,25.45 58.3,25.05 70.02,13.34
N$41
  Top 0.254: J2.29 72.37,15.87 64.91,23.32 64.91,31.83 62.5,34.2 57.89,34.2 57.7,34.39 57.6,34.29 U1.P29
N$42  (via drill 0.3)
  Top 0.254: BOOTST.8 62.68,85.74 55.19,85.74 v53.1,81.82 | R10.1 | v44.34,78.79 R10.1
  Bottom 0.254: v44.34,78.79 44.38,78.76 48.88,78.76 51.88,81.76 53.1,81.76 v53.1,81.82
N$43  (via drill 0.3)
  Top 0.254: v60.2,24.19 58.51,24.19 52.51,30.39 52.51,33.63 U1.P30
  Bottom 0.254: J2.30 66,18.41 v60.2,24.19
N$44  (via drill 0.3)
  Top 0.254: U1.P31 54.6,34.21 54.6,30.77 v56.69,28.68
  Bottom 0.254: J2.31 64.41,20.95 v56.69,28.68 | J2.31
N$45
  Top 0.254: J2.32 72.29,23.49 66.47,29.26 66.47,32.36 63.04,35.79 57.64,35.79 57.64,35.75 U1.P32
N$46  (via drill 0.3)
  Top 0.254: v62.18,24.27 61.35,23.43 58.42,23.43 51.86,29.98 51.86,34.5 53.59,36.22 U1.P33
  Bottom 0.254: J2.33 63.95,26.03 v62.18,24.27
N$47  (via drill 0.3)
  Top 0.254: U1.P34 56.6,35.71 56.6,31.51 v59.54,28.57
  Bottom 0.254: J2.34 v59.54,28.57
N$48
  Top 0.254: J2.35 69.75,31.11 63.66,37.2 57.74,37.2 57.71,37.23 57.7,37.21 U1.P35
N$49  (via drill 0.3)
  Top 0.254: R11.1 47.98,80.66 45.96,82.68 45.95,86.3 45.95,86.31 v46.79,87.16
  Bottom 0.254: BOOTST.6 65.23,85.73 61.23,85.73 61.23,85.74 59.19,85.74 56.58,88.34 48,88.34 47.26,87.6 v46.79,87.16
N$50
  Bottom 0.254: J2.36 61.79,33.65 58.5,30.36 54.74,30.36 51.69,33.41 51.69,35.85 53.57,37.73 53.59,37.71 U1.P36
N$51
  Bottom 0.254: U1.P37 54.6,37.21 54.6,33.28 56.49,31.39 58.26,31.39 63.06,36.19 J2.37 | J2.37 | J2.37
N$52
  Top 0.254: J2.38 74.14,38.74 | J2.38 | U1.P38 74.11,38.71 J2.38
N$53  (via drill 0.3)
  Top 0.254: v31.77,27.06 33.04,28.33 37.66,28.33 38.07,28.73 38.17,28.73 38.17,28.74 U1.P2
  Bottom 0.254: J1.2 15.71,4.33 19.83,8.45 29.02,8.45 31.77,11.2 v31.77,27.06
N$54
  Bottom 0.254: 74.25,41.27 J2.39 72.06,41.28 68.62,44.72 61.86,44.72 59.81,46.76 55.21,46.76 52.08,43.63 52.08,40.74 U1.P39
N$55  (via drill 0.3)
  Top 0.254: v58.93,45.93 61.91,45.93 v61.93,45.91
  Bottom 0.254: U1.P40 56.6,40.71 56.6,45.21 57.32,45.93 v58.93,45.93 | v61.93,45.91 68.84,45.91 70.93,43.81 J2.40 | J2.40
N$56
  Top 0.254: J2.41 | J2.41 74.18,46.34 | J2.41 69.79,46.34 63.65,40.2 57.79,40.2 57.6,40.02 U1.P41
N$58  (via drill 0.3)
  Top 0.254: U1.P43 56.61,42.22 56.61,45.21 58.77,47.36 v62.4,47.36
  Bottom 0.254: v62.4,47.36 68.56,47.36 72.63,51.44 74.18,51.44 | 74.18,51.44 74.17,51.43 J2.43 | 74.18,51.44 74.22,51.48
N$59
  Top 0.254: U1.P44 63.33,41.71 66.3,44.69 66.3,49.7 70.55,53.95 74.27,53.95 74.25,53.97 J2.44
N$60  (via drill 0.3)
  Top 0.254: U1.P45 53.6,42.28 52.61,43.27 52.61,44.32 57.04,48.74 57.04,50.32 60.24,53.53 60.25,53.53 v60.27,53.52
  Bottom 0.254: v60.27,53.52 61.03,54.27 70.38,54.27 72.63,56.52 J2.45 | J2.45 74.18,56.52 | J2.45
N$62
  Top 0.254: U1.P47 62.99,43.21 65.02,45.24 65.02,54.4 72.17,61.55 74.09,61.55 J2.47
N$63  (via drill 0.3)
  Top 0.254: U1.P48 53.6,44.54 59.48,50.4 61.27,52.19 61.27,56.17 61.26,56.18 v67.55,62.47
  Bottom 0.254: v67.55,62.47 70.81,62.47 72.43,64.09 74.07,64.09 74.11,64.13 J2.48
N$64  (via drill 0.3)
  Top 0.254: v71.07,66.71 71.07,64.12 62.89,55.93 62.89,55.88 62.87,55.87 62.87,52.27 55.6,45 U1.P49
  Bottom 0.254: J2.49 74.09,66.71 v71.07,66.71
N$65
  Top 0.254: U1.P50 62.61,44.71 63.65,45.75 63.65,55.56 71.93,63.81 71.93,67 74.15,69.21 | 74.15,69.21 74.27,69.34 | 74.15,69.21 J2.50
N$66
  Top 0.254: J3.51 65.3,65.46 50.57,65.46 49.68,64.57 49.68,52.72 49.62,52.66 | 49.62,52.66 49.62,52.65 | U1.P51 49.62,52.66
N$67
  Bottom 0.254: U1.P52 49.15,48.69 49.25,48.8 50.61,48.8 59.88,58.07 71.59,69.78 71.59,71.12 | 71.59,74.33 J3.52 | 71.59,71.13 71.59,74.33 | 71.59,74.33 71.68,74.41
  Bottom 0.305: 71.59,71.12 71.59,71.13
N$68
  Bottom 0.254: U1.P53 51.47,50.66 63.71,62.88 63.71,66.21 69.07,71.6 69.07,74.27 J3.53 | J3.53 | J3.53
N$70
  Top 0.254: 66.66,74.29 66.67,74.3 | 66.66,74.29 J3.54 | 66.66,74.29 66.53,74.16 66.53,72.25 60.92,66.63 49.82,66.63 48.25,65.05 48.25,52.79 48.15,52.69 U1.P54
N$71  (via drill 0.3)
  Top 0.254: U1.P55 48.67,47.64 49.59,47.64 54.55,52.6 v54.55,64.13 | v60.02,69.61 61.46,69.61 63.97,72.13 J3.55
  Bottom 0.254: v54.55,64.13 v60.02,69.61 | v60.02,69.61
N$72  (via drill 0.3)
  Top 0.254: U1.P56 48.15,49.67 49.84,49.67 53.33,53.16 v53.33,53.93
  Bottom 0.254: v53.33,53.93 61.39,61.94 61.39,65.27 61.43,65.37 J3.56 | J3.56 61.43,74.3 | J3.56
N$73
  Top 0.254: J3.57 58.89,74.28 58.93,74.23 58.86,74.16 58.86,72.18 54.55,67.86 49.27,67.86 46.67,65.26 46.67,52.72 46.65,52.7 U1.P57
N$74  (via drill 0.3)
  Top 0.254: U1.P58 47.79,47.03 49.84,47.03 56,53.18 v56,61.6
  Bottom 0.254: v56,61.6 54.56,61.6 53.47,62.7 53.47,69.3 56.33,72.17 56.33,74.32 56.35,74.31 J3.58
N$75  (via drill 0.3)
  Top 0.254: v51.61,52.66 52.37,53.42 v52.37,63.96
  Bottom 0.254: U1.P59 46.65,51.66 50.61,51.66 v51.61,52.66 | v51.61,52.66 | J3.59 52.37,72.84 v52.37,63.96
N$78  (via drill 0.3)
  Top 0.254: U1.P62 45.15,51.66 50.18,51.66 50.89,52.37 50.89,63.92 v50.87,63.93
  Bottom 0.254: v50.87,63.93 50.87,63.99 46.19,68.67 46.19,74.28 J3.62
N$79
  Top 0.254: 43.71,74.29 43.72,74.3 | 43.71,74.29 J3.63 | U1.P63 43.65,74.23 43.71,74.29
N$80  (via drill 0.3)
  Top 0.254: U1.P80 35.06,44.07 35.06,46.02 33.6,47.49 33.59,47.49 v30.86,50.22
  Bottom 0.254: J4.80 22.04,59.05 22.04,59.03 v30.85,50.22 v30.86,50.22
N$81
  Top 0.254: U1.P79 23.91,43.21 22.24,44.87 22.24,53.33 20.86,54.71 18.71,54.71 16.62,56.8 16.62,59.93 15,61.55 13.26,61.55 13.22,61.59 J4.79
N$83  (via drill 0.3)
  Top 0.254: v36.48,48.32 36.46,48.33 v35.14,49.76
  Bottom 0.254: U1.P64 42.11,47.62 37.29,47.62 v36.48,48.32 | J3.64 39.75,75.65 27.87,75.65 27.14,74.91 27.14,58.39 27.14,58.1 27.47,57.77 35.14,50.1 v35.14,49.76
N$84  (via drill 0.3)
  Top 0.254: U1.P78 31.7,45.33 v27.05,49.99 | v22.64,54.39 22.64,55.67 14.26,64.11 13.17,64.11 J4.78
  Bottom 0.254: v27.05,49.99 27.05,50 v22.64,54.39
N$86  (via drill 0.3)
  Top 0.254: U1.P77 33.7,45.99 v29.63,50.06 | 13.02,66.67 13.01,66.68 | 13.02,66.67 J4.77 | v22.15,57.53 v22.15,57.54 13.02,66.67
  Bottom 0.254: v29.63,50.06 v22.15,57.53
N$87  (via drill 0.3)
  Top 0.254: v35.39,52.4 35.6,52.34 35.6,63.37 v35.61,63.38 v35.6,63.38
  Bottom 0.254: U1.P65 41.66,49.67 37.43,49.67 37.43,49.68 35.78,51.33 35.78,52.03 35.42,52.4 | J3.65 | J3.65 | v35.6,63.38 38.57,66.3 J3.65 | 35.42,52.4 | 35.42,52.4 v35.39,52.4
N$88
  Top 0.254: U1.P66 42.15,66.15 36.05,72.25 36.05,74.1 36.12,74.16 36.03,74.25 J3.66
N$89  (via drill 0.3)
  Top 0.254: v33.45,57.79 33.45,54.25 v33.45,54.34 | v36.31,49.75 36.38,49.67 40.63,49.68 U1.P67
  Bottom 0.254: J3.67 33.49,57.83 v33.45,57.79 | v33.45,54.34 33.45,52.61 v36.31,49.75
N$90
  Bottom 0.254: U1.P68 40.16,51.65 37.19,51.65 30.96,57.88 30.96,74.3 | 30.96,74.3 30.96,74.31 | 30.96,74.3 J3.68
N$91
  Top 0.254: U1.P69 40.65,65.11 37.9,67.86 32.76,67.86 28.38,72.25 28.38,74.3 28.39,74.29 J3.69
N$92  (via drill 0.3)
  Top 0.254: v34.02,49.77 34.02,48.96 35.37,47.62 39.1,47.62 40.15,48.67 U1.P70
  Bottom 0.254: J3.70 25.87,57.92 v34.02,49.77
N$93  (via drill 0.3)
  Top 0.254: U1.P71 38.66,51.65 35.08,51.71 v23.33,63.46
  Bottom 0.254: J3.71 v23.33,63.46
N$94
  Top 0.254: U1.P72 39.15,64.69 37.22,66.63 26.32,66.63 20.77,72.18 20.77,74.3 | 20.77,74.3 J3.72 | 20.77,74.3 20.71,74.37
N$95
  Bottom 0.254: J3.73 18.25,64.48 33.66,49.06 37.57,49.07 38.63,48.67 38.63,48.66 U1.P73
N$96  (via drill 0.3)
  Top 0.254: U1.P74 32.7,50.66 v15.69,67.68
  Bottom 0.254: J3.74 15.69,74.27 v15.69,67.68
N$97
  Top 0.254: J3.75 22.06,65.39 36.67,65.39 37.56,64.5 37.56,52.79 37.65,52.7 U1.P75
N$99
  Top 0.254: 35.9,3.17 35.85,3.12 | 35.9,3.17 J1.10 | 35.9,3.17 36.1,3.37 36.1,5.4 42.15,11.44 U1.P10 | U1.P10 | U1.P10
N$100
  Top 0.254: U1.P97 29.65,34.26 23.6,34.26 22.27,32.92 22.27,29.79 15.53,23.05 15.53,16.45 15,15.92 13.17,15.92 J4.97
N$102
  Top 0.254: 28.52,3.46 28.35,3.29 28.41,3.23 J1.7 | U1.P7 40.65,24.71 40.64,24.7 40.65,24.69 | 25.59,1.36 26.6,1.36 | 40.65,11.79 | C6.+ 6.69,11.53 6.61,11.45 6.51,11.55
  Top 0.305: 40.65,11.79 34.45,5.6 28.88,5.6 28.52,5.23 28.52,3.46 | 26.6,1.36 J1.7 | 40.65,24.69 40.65,22.29 41.3,21.64 41.3,12.44 40.65,11.79 | 25.59,1.36 8.12,1.36 3.67,5.81 3.67,10.84 4.38,11.55 6.51,11.55
P51
  Bottom 0.254: U1.P12 42.17,25.79 36.9,25.79 36.65,25.53 36.65,13.18 41.02,8.81 41.02,3.11 41.05,3.11 J1.12 | 43.65,86.84 47.6,82.89 57.04,82.89 58.11,81.82 73.76,81.82 76.59,79 76.59,2.61 75.13,1.16 41.77,1.16 41.09,2.04
  Bottom 0.406: 43.65,86.84 J6.1 | J1.12 41.11,3.13 41.09,3.11 41.09,2.04
RST/NMI  (via drill 0.3)
  Top 0.254: U1.P94 23.53,35.71 21,33.18 21,29.52 15,23.53 13.17,23.53 J4.94 | JTAG.11 20.34,89.08 66.65,89.08 66.66,89.07 68.77,89.07 70.31,87.53 70.31,85.72 BOOTST.4 | 4.43,60.25 C8.2 4.47,60.25 4.48,60.25 | v4.53,58.88 4.43,58.98 | R5.1 | R5.1 4.48,62.51 | R5.1 4.53,62.8
  Top 0.305: 4.43,58.98 4.43,60.25 | 4.53,62.8 v4.17,63.92 | 4.48,60.25 4.48,62.51
  Bottom 0.254: J4.94 | JTAG.11 16.97,85.71 10.3,85.71 7.67,83.07 7.67,81.8 6.51,80.64 4.48,80.64 4.17,80.34 v4.17,63.92 | J4.94 5.47,23.49 4.53,24.43 4.53,39.81 v4.53,58.88
TCK  (via drill 0.3)
  Top 0.254: U1.P93 30.7,35.21 30.7,32.09 29.2,30.63 v24.59,30.63 | v11.25,62.52 11.21,75.83 15.37,79.99 19.83,79.99 19.84,79.98 21.4,79.98 v24.6,83.28 | 14.43,26 | 14.43,26 14.43,26.03 15.2,26.81 15.2,29.14 16.63,30.56 16.63,30.57 v16.68,30.63 16.68,30.63 v16.68,49.93 | J4.93 14.4,26.03 14.43,26
  Bottom 0.254: BOOTST.2 72.8,85.67 73.22,86.09 73.22,87.64 71.8,89.07 25.41,89.07 JTAG.7 23.38,86.94 23.43,86.94 24.6,85.67 v24.6,83.28 | v16.68,30.63 v24.59,30.63 | v16.68,49.93 16.52,50.09 12,50.09 11.24,50.85 11.24,62.53 | 11.24,62.53 11.24,62.54 | 11.24,62.53 v11.25,62.52
TDI  (via drill 0.3)
  Top 0.254: v14.43,76.52 14.43,77.62 15.78,78.96 28.69,78.96 29.66,79.94 29.67,79.93 29.68,79.93 29.68,82.16 v29.67,82.17 | 19.37,57.95 v14.88,62.45 | 19.37,57.95 19.38,57.95 | 19.37,57.95 19.39,57.94 v19.39,55.61 | J4.91 13.26,31.11 15.76,33.61 v15.76,37.22 15.76,46.22 15.71,46.27 | 15.85,52.16 15.86,52.17 | 15.85,52.16 15.85,52.09 v15.89,52.13 15.89,51.84 15.71,51.66 15.71,46.27 | 15.85,52.16 15.76,52.07 | 15.71,46.27
  Bottom 0.254: JTAG.3 29.67,85.73 29.67,84.26 29.67,84.25 v29.67,82.17 | v14.43,76.52 v14.42,76.51 14.42,71.56 14.88,71.11 v14.88,62.45 | v15.89,52.13 15.89,52.33 | U1.P91 29.69,37.22 v15.76,37.22
  Bottom 0.305: v19.39,55.61 19.37,55.59 19.37,53.39 18.15,52.17 15.91,52.17 15.91,52.31 15.89,52.33
TDO  (via drill 0.3)
  Top 0.254: v25.44,31.48 v28.33,31.48 | JTAG.1 32.38,85.56 v32.38,76.69 | J4.90 13.19,33.62 14.99,35.41 14.99,44.46 15,44.47 15,59.08 15.66,59.74 v15.66,59.83 | v15.66,59.83 15.66,59.85 | v15.66,59.83 v15.65,59.82
  Bottom 0.254: U1.P90 30.68,36.69 30.68,32.29 29.86,31.47 29.85,31.48 v28.33,31.48 | 18.65,31.47 | v25.44,31.48 v25.44,31.47 18.65,31.47 | v32.38,76.69 17.97,76.69 16.98,75.7 16.98,61.17 v15.65,59.82 | 18.65,31.47 18.63,31.47 16.48,33.63 16.48,33.61 | 16.48,33.61 16.52,33.57 | J4.90 16.44,33.65 16.48,33.61
TMS  (via drill 0.3)
  Top 0.254: v60.18,55.13 59.73,54.72 54.69,49.68 54.69,47.86 52.51,45.67 42.64,45.67 42.64,45.65 U1.P92 35.38,35.04 35.38,32.39 29.79,26.76 v27.82,26.76 | v74.22,77.93 54.03,77.92 | v34.47,76.64 33.77,77.33 33.77,86.48 31.87,88.39 27.27,88.39 JTAG.5 | JTAG.5 | JTAG.5
  Top 0.305: 54.03,77.92 54,77.89 50.78,77.89 v50.76,77.92
  Bottom 0.254: J4.92 26,28.57 v27.82,26.76 | v60.18,55.13 65.75,60.71 70.51,60.71 72.68,62.87 75.25,62.87 75.44,63.05 75.44,76.95 74.8,77.89 74.25,77.89 74.74,77.92 | 74.74,77.92 74.74,77.93 | v50.76,77.92 50.73,77.92 49.47,76.65 43.59,76.65 43.59,76.64 v34.47,76.64 | v74.22,77.93 v74.22,77.92 74.22,77.89 74.71,77.89 74.74,77.92
VCC  (via drill 0.3)
  Top 0.254: 7.55,69.78 R9.1 | R10.2 42.44,80.61 42.39,80.56 | 49.89,80.63 49.87,80.63 R11.2 | 48.73,86.99 J7.2 | 2.65,65.49 R8.1 2.6,65.48 | 2.65,68.18 J5.1 2.34,68.49 | 2.6,62.49 2.6,62.51 R5.2
  Top 0.305: v8.02,71.15 7.55,69.78 6.25,68.49 2.34,68.49 | v39.87,80.56 42.39,80.56 | J7.2 50.44,85.27 50.44,83.1 49.89,82.55 49.89,80.63 | R10.2 42.46,83.26 41.65,84.07 41.65,87.62 42.46,88.43 47.29,88.43 48.73,86.99 | R8.1 2.65,68.18 | 2.6,62.51 2.6,65.48
  Bottom 0.305: v8.02,71.15 8.02,76.19 10.79,78.97 38.28,78.97 v39.87,80.56
XIN
  Top 0.254: 30.14,25.73 25.47,21.06 25.47,20.8 25.41,20.8 Q1.4 25.38,20.8 25.36,20.8 25.36,20.75 24.2,19.58 24.25,19.58 24.25,15.21 24.2,15.16 23.24,15.16 R12.1 22.67,14.55 22.67,12.38 | 22.67,12.38 22.67,12.31 | C2.1 22.67,12.38 | 41.12,28.79 41.12,28.89 | 41.12,28.79 U1.P8 | 41.12,28.79 41.12,28.73 40.11,27.72 34.61,27.77 32.58,25.73 30.14,25.73 | 30.14,25.73 30.14,25.74
XOUT  (via drill 0.3)
  Top 0.254: Q1.3 v27.94,20.78 32.99,20.75 33.04,20.8 33.04,22.48 36.29,25.73 40.66,25.73 40.66,25.77 U1.P9 | R4.1 22.54,19.89 22.57,19.89 22.57,18.77 v22.88,18.47 21.81,18.47 C1.1
  Bottom 0.254: v27.94,20.78 26.75,19.53 23.99,19.53 22.93,18.47 v22.88,18.47
XT2IN  (via drill 0.3)
  Top 0.254: Q2.P$1 9.36,55.24 9.36,46.73 8.75,46.12 | 8.75,46.12 8.75,46.17 C3.1 8.8,46.12 v8.8,44.8 | 8.75,46.12
  Bottom 0.254: U1.P89 35.34,36.57 35.34,32.46 31.61,28.74 27.96,28.72 26.44,30.25 26.44,31.93 25.67,32.7 20,32.7 16.5,36.19 16.5,36.18 | 16.5,36.18 | 16.5,36.18 16.49,36.19 J4.89 13.14,36.16 11.95,36.16 8.8,39.31 v8.8,44.8
XT2OUT  (via drill 0.3)
  Top 0.254: Q2.P$4 7.36,48.15 6,48.15 4.63,46.78 4.63,46.22 C4.1 | 29.67,38.73 29.67,38.72 29.68,38.71 U1.P88 | 29.67,38.73 | 29.67,38.7 29.68,38.69 | 29.67,38.7 29.67,38.73 | v25.73,38.73 29.64,38.73 29.67,38.7
  Bottom 0.254: Q2.P$4 9.88,47.1 9.88,42.01 13.15,38.73 J4.88 v25.73,38.73

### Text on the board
Top: MSP-TS430PZ100 | Rev.: 1.2
Bottom: 2 | 2
tNames: Open J6 if | LCD connected | 1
